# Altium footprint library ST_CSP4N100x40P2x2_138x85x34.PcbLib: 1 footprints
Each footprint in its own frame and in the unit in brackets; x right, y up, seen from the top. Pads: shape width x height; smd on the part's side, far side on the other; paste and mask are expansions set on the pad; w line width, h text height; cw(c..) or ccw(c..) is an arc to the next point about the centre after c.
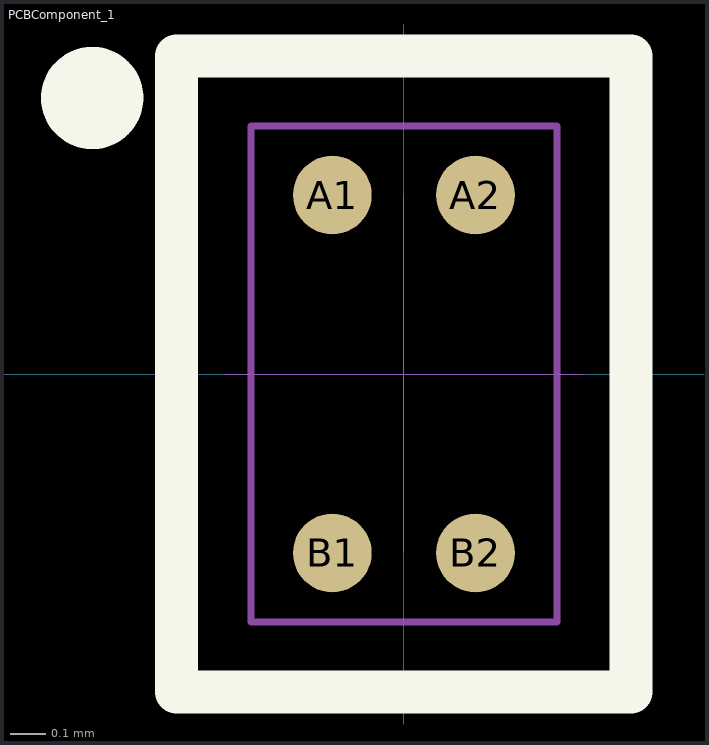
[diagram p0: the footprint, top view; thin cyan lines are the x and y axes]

## PCBComponent_1 [mm]
pads (4):
  round 0.22 smd paste+0 mask+0.05: A1(-0.2,0.5) A2(0.2,0.5) B1(-0.2,-0.5) B2(0.2,-0.5)
Top Overlay:
  circle w0.2: c-0.871,0.771 r0.043
  lines w0.12: -0.635,-0.889 -0.635,0.889 0.635,0.889 0.635,-0.889 -0.635,-0.889
Mechanical 15:
  lines w0.001: -0.5,0 0.5,0 ; 0,-0.5 0,0.5
  lines w0.02: -0.427,-0.693 -0.427,0.693 0.427,0.693 0.427,-0.693 -0.427,-0.693
3D body: height 0.38, standoff 0.12, extent -0.427,-0.693 0.427,0.693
